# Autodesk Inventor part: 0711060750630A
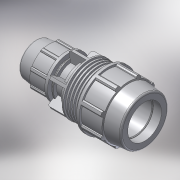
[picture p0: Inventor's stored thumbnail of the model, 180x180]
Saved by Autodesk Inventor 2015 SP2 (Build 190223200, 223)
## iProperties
Created: 2017-02
Part Number: 0711060750630A
Material: PVC-Piping
Description: PLASSON REDUCING COUPLER 75-63
Document SubType Name: Modeling
Designer: KIM
Mass: 92.6774 g
Surface Area: 199.44 cm^2
Volume: 66.1981 cm^3
Density: 1.4 g/cm^3
Appearance: Smooth - White
Author: KIM
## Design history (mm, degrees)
derived "87110.ipt"
feature "Solid1::87110.ipt"
tag "TaggingFeature1"
body "Solid1"
other parameters: "d2" = 75, "d4" = 21, "d5" = 36, "d7" = 134, "d9" = 36, "d11" = 3.6, "d12" = 107.2, "d13" = 120 deg, "d14" = 105, "d15" = 6 deg, "d16" = 120.6, "d18" = 3.75, "d19" = 35 deg, "d20" = 17.5 deg, "d21" = 124.62, "d23" = 0, "d25" = 360 deg, "d27" = 2.68, "d42" = 55.44, "d46" = 1.5, "d51" = 252, "d52" = 36, "d53" = 8 deg, "d54" = 132, "d56" = 88.2, "d57" = 63, "d58" = 67.5, "d59" = 56.7, "d60" = 101.7, "d61" = 90.4, "d62" = 31.5, "d63" = 45.36, "d64" = 120 deg, "d65" = 113, "d68" = 18, "d74" = 105.09, "d75" = 35 deg, "d76" = 17.5 deg, "d78" = 0, "d80" = 360 deg, "d85" = 2.26, "d88" = 1.26, "d93" = 112, "d94" = 93.8, "d98" = 7.53333, "d99" = 0, "d100" = 5.36, "d102" = 360 deg, "d104" = 2, "d106" = 0, "d107" = 7.53333, "d108" = 0, "d109" = 7.53333, "d110" = 0, "d111" = 3.33333, "d112" = 3.33333, "d113" = 3.33333, "d114" = 2.296, "d116" = 2.296, "d119" = 4.592, "d125" = 118.188, "d_" = 75, "E_" = 134, "H_" = 252, "l_" = 132, "d_1" = 63, "E_1" = 113, "l_1" = 112, "d96" = 10, "d115" = 22.96
